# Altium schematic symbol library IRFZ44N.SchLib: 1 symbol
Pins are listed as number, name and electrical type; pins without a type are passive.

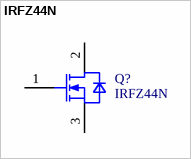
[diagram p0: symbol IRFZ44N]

## IRFZ44N
designator Q?
OptiMOS 3 Power-Transistor, VDS 100V; Manufacturer: Infineon Technologies
footprint IFX-PG-TO220-3-904-1 (TO,flange mount,2.54 mm pitch, 3 pin, 10.16 mm L X 4.57 mm W X 20.56 mm H body)
pins: 1 GATE, 2 DRAIN, 3 SOURCE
